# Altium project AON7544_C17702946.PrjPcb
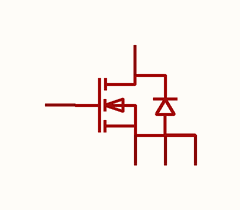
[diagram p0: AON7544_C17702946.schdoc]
1 sheet, 1 parts. Net scope: global (net labels, ports and power ports of the same name join across sheets).

## Sheet AON7544_C17702946.schdoc
size 127 x 101 mm

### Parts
Q?  aon7544_c17702946  [POWERDI3333-8_DMN7022LFGQ-7]  (value not drawn)

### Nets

Not connected (* = marked no-connect by the designer): Q? 1(S) 2(S) 3(S) 4(G) 5(D)

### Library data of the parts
Q? = aon7544_c17702946: 数量:1个N沟道;漏源电压(Vdss):30V;连续漏极电流(Id):100A;导通电阻(RDS(on)):4mΩ@10V;耗散功率(Pd):62.5W;阈值电压(Vgs(th)):2.5V;; Manufacturer: MSKSEMI(美森科); AddInBom: yes; ModelId: 296e462280334ba794f41fc0f4558c2c; ModelTransform: 130.708,130.708,0,0,0,0,0,18.625,0; Number: 1个N沟道; Drain to Source Voltage: 30V; Current - Continuous Drain(Id): 100A; Pd - Power Dissipation: 62.5W; Gate Threshold Voltage (Vgs(th)): 2.5V; Gate Charge(Qg): 31.6nC@15V; Input Capacitance(Ciss): 3.075nF; Reverse Transfer Capacitance (Crss@Vds): 315pF; Output Capacitance(Coss): 400pF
